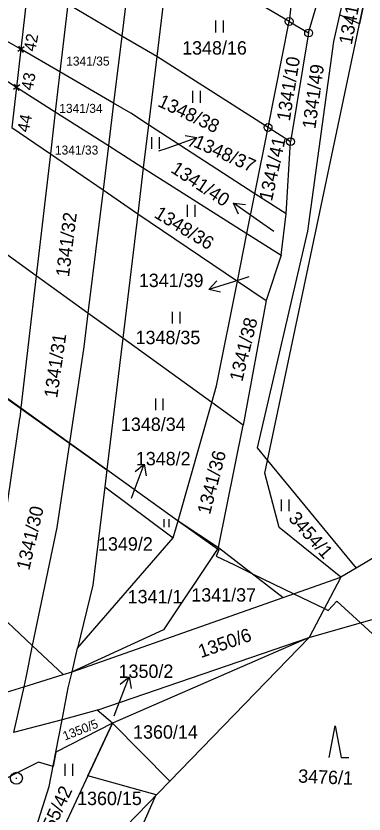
# Model space of a CAD drawing. Extents: x -735036 to -734743, y -1144813 to -1144181.
# Drawn here: x -734846.3 to -734802.1, y -1144707.5 to -1144606.2 of the extents above; entities that cross this region are included whole.
import ezdxf

# ---------------------------------------------------------------- set-up
doc = ezdxf.new("R2010")
doc.units = 0
for name, color, linetype in [('BPEJ', 7, 'Continuous'), ('Groma (60)', 7, 'Continuous'), ('Katastr_HRANICE DRÁHY', 7, 'Continuous'), ('Katastr_Hranice parcel', 7, 'Continuous'), ('Katastr_Parcelní čísla', 7, 'Continuous'), ('Katastr_Slučkované čáry', 7, 'Continuous'), ('Katastr_Značky kultur', 7, 'Continuous')]:
    doc.layers.add(name, color=color, linetype=linetype)

# ---------------------------------------------------------------- blocks, each defined once
blk = doc.blocks.new('POINT_DISPLAY')
for p, q in [((-0.35, -0.35), (0.35, 0.35)), ((-0.35, 0.35), (0.35, -0.35))]:
    blk.add_line(p, q)

msp = doc.modelspace()

# ---------------------------------------------------------------- linework, layer by layer
at = {"layer": 'BPEJ'}
for points in [[(-734799.83, -1144593.94), (-734802.63, -1144607.21), (-734805.16, -1144606.06)], [(-734886.95, -1144596.85), (-734888.29, -1144609.47), (-734890, -1144625.5), (-734887.82, -1144626.59), (-734885, -1144628), (-734852.91, -1144650.88), (-734852.15, -1144651.42), (-734850.43, -1144652.65), (-734834.73, -1144663.85), (-734834.99, -1144666), (-734826.29, -1144672.48), (-734825.67, -1144670.31), (-734820.68, -1144673.87), (-734820.5, -1144674), (-734820.82, -1144674.78), (-734818.52, -1144675.9), (-734816.23, -1144677.02), (-734810.97, -1144679.57), (-734807.09, -1144681.45), (-734806.63, -1144681.68), (-734805.5, -1144680.5), (-734802.5, -1144683.25), (-734799.5, -1144686)], [(-734875.41, -1144811.46), (-734872.9, -1144805.78), (-734867.89, -1144794.43), (-734854.34, -1144763.72), (-734850.2, -1144754.32), (-734842.33, -1144736.48), (-734836.55, -1144723.38), (-734836.47, -1144723.21), (-734828.55, -1144705.26), (-734828.47, -1144705.07), (-734837.14, -1144702.69), (-734834.01, -1144696), (-734841.2, -1144699.67), (-734841.55, -1144701.48), (-734843.42, -1144700.96), (-734850.5, -1144704.5), (-734856.16, -1144706.13), (-734861.05, -1144707.56), (-734878.02, -1144712.44), (-734888.06, -1144715.34), (-734896.33, -1144716.95), (-734914.06, -1144720.39), (-734915.89, -1144720.74)]]:
    msp.add_lwpolyline(points, dxfattribs=at)
at = {"layer": 'Katastr_HRANICE DRÁHY'}
for points in [[(-734844.66, -1144601.82), (-734845.64, -1144610.44)], [(-734845.64, -1144610.44), (-734846.19, -1144615.27)], [(-734828.38, -1144611.37), (-734829.43, -1144620.02)], [(-734814.25, -1144620.37), (-734828.38, -1144611.37)], [(-734846.19, -1144615.27), (-734846.77, -1144620.37)], [(-734829.43, -1144620.02), (-734830.09, -1144625.49)], [(-734815.92, -1144628.78), (-734814.25, -1144620.37)], [(-734830.09, -1144625.49), (-734830.79, -1144631.32)], [(-734816.93, -1144633.84), (-734815.92, -1144628.78)], [(-734830.79, -1144631.32), (-734832.7, -1144647.12)], [(-734818.13, -1144639.88), (-734816.93, -1144633.84)], [(-734818.13, -1144639.88), (-734814.48, -1144642.35)], [(-734814.48, -1144642.35), (-734817.41, -1144658.17)], [(-734832.7, -1144647.12), (-734834.72, -1144663.79)], [(-734825.66, -1144670.29), (-734821.38, -1144655.27)], [(-734817.41, -1144658.17), (-734821.38, -1144655.27)], [(-734834.72, -1144663.79), (-734834.99, -1144666)], [(-734834.99, -1144666), (-734826.29, -1144672.48)], [(-734826.29, -1144672.48), (-734825.66, -1144670.29)]]:
    msp.add_lwpolyline(points, dxfattribs=at)
at = {"layer": 'Katastr_Hranice parcel'}
for points in [[(-734798.65, -1144577.31), (-734805.94, -1144609.48)], [(-734814.3, -1144662.64), (-734799.83, -1144593.94)], [(-734826.76, -1144597.94), (-734828.38, -1144611.37)], [(-734811.57, -1144606.92), (-734826.76, -1144597.94)], [(-734809.1, -1144608.38), (-734806.45, -1144599.27)], [(-734811.14, -1144603.11), (-734811.57, -1144606.92)], [(-734832.82, -1144608.77), (-734839.69, -1144604.74)], [(-734814.25, -1144620.37), (-734811.57, -1144606.92)], [(-734811.57, -1144606.92), (-734809.1, -1144608.38)], [(-734845.64, -1144610.44), (-734847.79, -1144609.19)], [(-734828.38, -1144611.37), (-734832.82, -1144608.77)], [(-734809.1, -1144608.38), (-734811.4, -1144622.18)], [(-734805.94, -1144609.48), (-734809.25, -1144633.53)], [(-734840.68, -1144613.32), (-734845.64, -1144610.44)], [(-734833.86, -1144617.29), (-734840.68, -1144613.32)], [(-734848.33, -1144613.91), (-734846.19, -1144615.27)], [(-734846.19, -1144615.27), (-734841.27, -1144618.39)], [(-734831.69, -1144618.55), (-734833.86, -1144617.29)], [(-734841.27, -1144618.39), (-734834.52, -1144622.68)], [(-734829.43, -1144620.02), (-734831.69, -1144618.55)], [(-734846.77, -1144620.37), (-734841.89, -1144623.71)], [(-734815.92, -1144628.78), (-734829.43, -1144620.02)], [(-734811.4, -1144622.18), (-734814.25, -1144620.37)], [(-734811.96, -1144631.35), (-734811.4, -1144622.18)], [(-734834.52, -1144622.68), (-734830.09, -1144625.49)], [(-734841.89, -1144623.71), (-734835.21, -1144628.29)], [(-734830.09, -1144625.49), (-734816.93, -1144633.84)], [(-734835.21, -1144628.29), (-734830.79, -1144631.32)], [(-734811.96, -1144631.35), (-734815.92, -1144628.78)], [(-734830.79, -1144631.32), (-734818.13, -1144639.88)], [(-734812.59, -1144636.59), (-734811.96, -1144631.35)], [(-734809.25, -1144633.53), (-734815.62, -1144661.04)], [(-734816.93, -1144633.84), (-734812.59, -1144636.59)], [(-734843.69, -1144639.2), (-734848.51, -1144635.73)], [(-734812.59, -1144636.59), (-734814.48, -1144642.35)], [(-734837.12, -1144643.94), (-734843.69, -1144639.2)], [(-734820.78, -1144653.18), (-734818.13, -1144639.88)], [(-734744.09, -1144641.26), (-734803.06, -1144676.31)], [(-734832.7, -1144647.12), (-734837.12, -1144643.94)], [(-734821.38, -1144655.27), (-734832.7, -1144647.12)], [(-734850.42, -1144652.54), (-734845.63, -1144655.97)], [(-734821.38, -1144655.27), (-734820.78, -1144653.18)], [(-734845.63, -1144655.97), (-734839.45, -1144660.4)], [(-734820.55, -1144673.68), (-734817.41, -1144658.17)], [(-734839.45, -1144660.4), (-734834.72, -1144663.79)], [(-734815.62, -1144661.04), (-734814.3, -1144662.64)], [(-734814.64, -1144664.24), (-734814.3, -1144662.64)], [(-734814.3, -1144662.64), (-734803.06, -1144676.31)], [(-734834.72, -1144663.79), (-734825.66, -1144670.29)], [(-734812.84, -1144671.15), (-734814.64, -1144664.24)], [(-734834.99, -1144666), (-734836.51, -1144678.49)], [(-734825.66, -1144670.29), (-734820.55, -1144673.68)], [(-734805.01, -1144677.47), (-734812.84, -1144671.15)], [(-734838.43, -1144686.49), (-734826.29, -1144672.48)], [(-734820.55, -1144673.68), (-734827.54, -1144684.16)], [(-734820.55, -1144673.68), (-734812.31, -1144680.04)], [(-734803.06, -1144676.31), (-734805.01, -1144677.47)], [(-734812.31, -1144680.04), (-734805.01, -1144677.47)], [(-734805.01, -1144677.47), (-734809.02, -1144685.13)], [(-734836.51, -1144678.49), (-734838.43, -1144686.49)], [(-734839.14, -1144689.47), (-734812.31, -1144680.04)], [(-734844.19, -1144686.14), (-734849.69, -1144680.98)], [(-734809.02, -1144685.13), (-734792.32, -1144680.32)], [(-734827.54, -1144684.16), (-734839.14, -1144689.47)], [(-734835.97, -1144694.36), (-734809.02, -1144685.13)], [(-734809.02, -1144685.13), (-734834.01, -1144696)], [(-734826.71, -1144703.36), (-734809.02, -1144685.13)], [(-734840.27, -1144689.82), (-734844.19, -1144686.14)], [(-734839.14, -1144689.47), (-734838.43, -1144686.49)], [(-734845.28, -1144691.36), (-734840.27, -1144689.82)], [(-734840.27, -1144689.82), (-734839.14, -1144689.47)], [(-734839.64, -1144691.51), (-734839.14, -1144689.47)], [(-734852.46, -1144693.56), (-734845.28, -1144691.36)], [(-734840.41, -1144695.55), (-734839.64, -1144691.51)], [(-734835.97, -1144694.36), (-734840.41, -1144695.55)], [(-734834.01, -1144696), (-734835.97, -1144694.36)], [(-734840.41, -1144695.55), (-734846.56, -1144697.19)], [(-734834.01, -1144696), (-734843.82, -1144716.99)], [(-734841.2, -1144699.67), (-734840.41, -1144695.55)], [(-734834.01, -1144696), (-734841.2, -1144699.67)], [(-734834.01, -1144696), (-734826.71, -1144703.36)], [(-734842.04, -1144704.04), (-734841.2, -1144699.67)], [(-734832.35, -1144709.16), (-734826.71, -1144703.36)], [(-734845.64, -1144715.39), (-734842.04, -1144704.04)]]:
    msp.add_lwpolyline(points, dxfattribs=at)
at = {"layer": 'Katastr_Parcelní čísla'}
for p, q in [((-734824.77, -1144621.39), (-734823.3, -1144621.66)), ((-734828.1, -1144623.35), (-734827.07, -1144622.99)), ((-734817.99, -1144631.36), (-734818.63, -1144630)), ((-734813.52, -1144633.57), (-734815.35, -1144632.29)), ((-734816.67, -1144639.35), (-734817.95, -1144639.75)), ((-734820.3, -1144641.27), (-734821.77, -1144640.94)), ((-734831.13, -1144664.06), (-734829.97, -1144663.11)), ((-734831.6, -1144667.41), (-734831.39, -1144666.85)), ((-734833.04, -1144691.04), (-734831.87, -1144690.11)), ((-734833.8, -1144695.04), (-734833.33, -1144693.83))]:
    msp.add_line(p, q, dxfattribs=at)
for points in [[(-734827.07, -1144622.99), (-734823.3, -1144621.66), (-734824.27, -1144622.8)], [(-734815.35, -1144632.29), (-734818.63, -1144630), (-734817.13, -1144630.13)], [(-734817.95, -1144639.75), (-734821.77, -1144640.94), (-734820.75, -1144639.84)], [(-734831.39, -1144666.85), (-734829.97, -1144663.11), (-734829.73, -1144664.59)], [(-734833.33, -1144693.83), (-734831.87, -1144690.11), (-734831.65, -1144691.59)]]:
    msp.add_lwpolyline(points, dxfattribs=at)
at = {"layer": 'Katastr_Slučkované čáry'}
for points in [[(-734831.41, -1144597.28), (-734832.82, -1144608.77)], [(-734839.69, -1144604.74), (-734840.68, -1144613.32)], [(-734832.82, -1144608.77), (-734833.86, -1144617.29)], [(-734840.68, -1144613.32), (-734841.27, -1144618.39)], [(-734833.86, -1144617.29), (-734834.52, -1144622.68)], [(-734841.27, -1144618.39), (-734841.89, -1144623.71)], [(-734834.52, -1144622.68), (-734835.21, -1144628.29)], [(-734841.89, -1144623.71), (-734843.69, -1144639.2)], [(-734835.21, -1144628.29), (-734837.12, -1144643.94)], [(-734843.69, -1144639.2), (-734845.63, -1144655.97)], [(-734837.12, -1144643.94), (-734837.64, -1144648.22)], [(-734837.64, -1144648.22), (-734839.11, -1144658.14)], [(-734845.63, -1144655.97), (-734845.78, -1144657.26)], [(-734848.46, -1144675.36), (-734845.78, -1144657.26)], [(-734839.11, -1144658.14), (-734839.45, -1144660.4)], [(-734839.45, -1144660.4), (-734841.08, -1144671.17)], [(-734841.08, -1144671.17), (-734844.19, -1144686.14)], [(-734844.19, -1144686.14), (-734845.03, -1144690.2)], [(-734845.03, -1144690.2), (-734845.28, -1144691.36)], [(-734845.28, -1144691.36), (-734846.56, -1144697.19)]]:
    msp.add_lwpolyline(points, dxfattribs=at)
at = {"layer": 'Katastr_Značky kultur'}
for p, q in [((-734820.92, -1144606.81), (-734820.92, -1144608.31)), ((-734819.92, -1144608.31), (-734819.92, -1144606.81)), ((-734811.62, -1144606.92), (-734811.52, -1144606.92)), ((-734809.15, -1144608.38), (-734809.05, -1144608.38)), ((-734823.84, -1144615.74), (-734823.84, -1144617.24)), ((-734822.84, -1144617.24), (-734822.84, -1144615.74)), ((-734814.3, -1144620.37), (-734814.2, -1144620.37)), ((-734829.05, -1144621.59), (-734829.05, -1144623.09)), ((-734828.05, -1144623.09), (-734828.05, -1144621.59)), ((-734811.45, -1144622.18), (-734811.35, -1144622.18)), ((-734824.51, -1144630.2), (-734824.51, -1144631.7)), ((-734823.51, -1144631.7), (-734823.51, -1144630.2)), ((-734826.41, -1144643.77), (-734826.41, -1144645.27)), ((-734825.41, -1144645.27), (-734825.41, -1144643.77)), ((-734828.55, -1144654.77), (-734828.55, -1144656.27)), ((-734827.55, -1144656.27), (-734827.55, -1144654.77)), ((-734812.58, -1144667.6), (-734812.58, -1144669.1)), ((-734811.58, -1144669.1), (-734811.58, -1144667.6)), ((-734827.47, -1144670.09), (-734827.47, -1144671.09)), ((-734826.81, -1144671.09), (-734826.81, -1144670.09)), ((-734840.05, -1144701.17), (-734840.05, -1144702.67)), ((-734839.05, -1144702.67), (-734839.05, -1144701.17)), ((-734846.26, -1144702.98), (-734846.16, -1144702.98))]:
    msp.add_line(p, q, dxfattribs=at)
msp.add_lwpolyline([(-734806.48, -1144700.34), (-734805.73, -1144696.34), (-734804.98, -1144700.34), (-734803.98, -1144700.34)], dxfattribs=at)
for centre, radius in [((-734811.57, -1144606.92), 0.499), ((-734809.1, -1144608.38), 0.499), ((-734814.25, -1144620.37), 0.499), ((-734811.4, -1144622.18), 0.499), ((-734846.21, -1144702.98), 0.756)]:
    msp.add_circle(centre, radius, dxfattribs=at)

# ---------------------------------------------------------------- block references
at = {"layer": 'Groma (60)', "rotation": -98.65482414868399}
for p in [(-734845.64, -1144610.44), (-734846.19, -1144615.27)]:
    msp.add_blockref('POINT_DISPLAY', p, dxfattribs=at)

# ---------------------------------------------------------------- texts
at = {"layer": 'Groma (60)'}
for s, rotation, p in [('42', 79.4999, (-734843.82, -1144610.81)), ('43', 80.0718, (-734844.14, -1144615.74)), ('44', 77.9946, (-734844.67, -1144621.07))]:
    msp.add_text(s, height=1.5, rotation=rotation, dxfattribs=at).set_placement(p)
at = {"layer": 'Katastr_Parcelní čísla'}
for s, height, rotation, p in [('1341/50', 1.7, 79.1371, (-734803.62, -1144609.95)), ('1341/10', 1.7, 80.8033, (-734811.49, -1144619.64)), ('1341/49', 1.7, 82.2448, (-734808.24, -1144620.62)), ('1348/38', 1.7, 334.718, (-734828.38, -1144617.62)), ('1348/37', 1.7, 335.921, (-734823.83, -1144622.77)), ('1341/41', 1.7, 77.5667, (-734813.76, -1144629.81)), ('1341/40', 1.7, 326.5752, (-734826.72, -1144625.98)), ('1348/36', 1.7, 328.6787, (-734828.83, -1144631.71)), ('1341/32', 1.7, 82.9954, (-734839.53, -1144639.41)), ('1341/38', 1.7, 76.1334, (-734817.53, -1144652.73)), ('1341/31', 1.7, 81.8408, (-734841.03, -1144654.79)), ('1341/36', 1.7, 75.4378, (-734821.63, -1144669.6)), ('1341/30', 1.7, 76.934, (-734844.58, -1144676.67)), ('3454/1', 1.7, 311.6778, (-734811.76, -1144670.07)), ('1350/6', 1.7, 18.9765, (-734822.77, -1144687.74)), ('1350/5', 1.14, 21.41, (-734840.05, -1144698.21)), ('3476/1', 1.7, 357.5604, (-734810.45, -1144703.53)), ('1355/42', 1.7, 65.118, (-734842.51, -1144711.93))]:
    msp.add_text(s, height=height, rotation=rotation, dxfattribs=at).set_placement(p)
for s, height, p in [('1348/16', 1.7, (-734825.16, -1144611.12)), ('1341/35', 1.14, (-734839.89, -1144612.52)), ('1341/34', 1.14, (-734840.77, -1144618.52)), ('1341/33', 1.14, (-734841.32, -1144623.81)), ('1341/39', 1.7, (-734830.66, -1144640.63)), ('1348/35', 1.7, (-734831.07, -1144647.88)), ('1348/34', 1.7, (-734832.93, -1144658.9)), ('1348/2', 1.7, (-734831.04, -1144663.26)), ('1349/2', 1.7, (-734835.84, -1144674.09)), ('1341/1', 1.7, (-734832.08, -1144680.78)), ('1341/37', 1.7, (-734823.99, -1144680.56)), ('1350/2', 1.7, (-734833.23, -1144690.25)), ('1360/14', 1.7, (-734831.39, -1144697.96)), ('1360/15', 1.7, (-734838.5, -1144706.39))]:
    msp.add_text(s, height=height, dxfattribs=at).set_placement(p)

doc.saveas('drawing.dxf')
